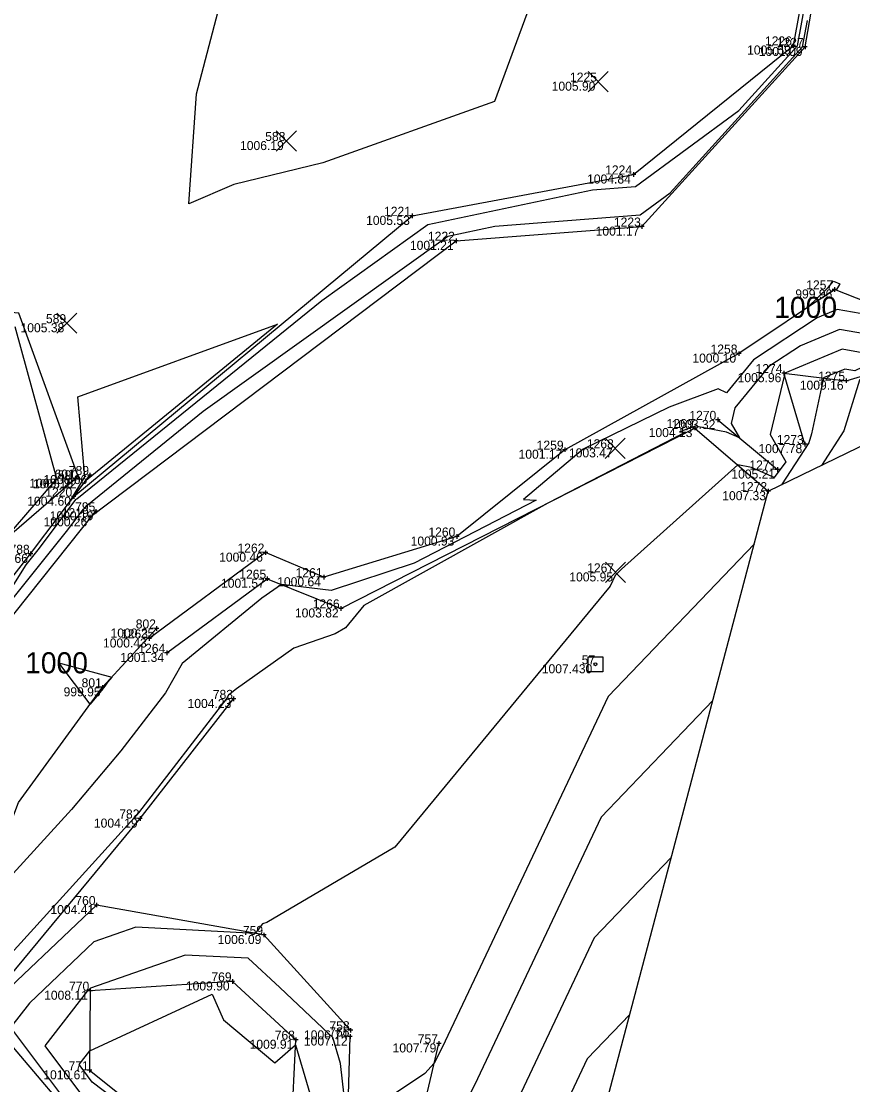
# Model space of a CAD drawing. Extents: x 2354693 to 2355622, y 637071 to 710080.
# Drawn here: x 2355435.7 to 2355546, y 709334.6 to 709475.6 of the extents above; entities that cross this region are included whole.
import ezdxf

# ---------------------------------------------------------------- set-up
doc = ezdxf.new("R2010")
doc.units = 0
for name, color, linetype in [('Default', 7, 'Continuous'), ('DR_X_Ditch', 7, 'Continuous'), ('DT_X_Contour_Major', 7, 'Continuous'), ('DT_X_Contour_Minor', 7, 'Continuous'), ('HY_X_Water_Edge', 7, 'Continuous'), ('SV_X_Control_Cells_Found', 7, 'Continuous'), ('SV_X_Random_Point', 7, 'Continuous'), ('SV_X_Shot_Marker', 7, 'Continuous'), ('SV_X_Text_Elevation', 7, 'Continuous'), ('SV_X_Text_Name', 7, 'Continuous'), ('SV_X_Toe_of_Slope', 7, 'Continuous'), ('SV_X_Top_of_Bank', 7, 'Continuous')]:
    doc.layers.add(name, color=color, linetype=linetype)

msp = doc.modelspace()

# ---------------------------------------------------------------- linework, layer by layer
at = {"layer": 'Default'}
msp.add_lwpolyline([(2355263.76, 708986.4), (2355330.91, 709003.61), (2355347.35, 709002.09), (2355387.45, 709051.54), (2355402.1, 709089.16), (2355425.96, 709130.16), (2355495.56, 709194.41), (2355530.33, 709221.46), (2355525, 709302.12), (2355509.66, 709318.33), (2355534.8, 709413.26), (2355566.11, 709428.47), (2355585.74, 709473.78), (2355589.64, 709532.44), (2355608.23, 709591.27)], dxfattribs=at)
msp.add_lwpolyline([(2355263.76, 708986.4), (2355330.91, 709003.61), (2355347.35, 709002.09), (2355387.45, 709051.54), (2355402.1, 709089.16), (2355425.96, 709130.16), (2355495.56, 709194.41), (2355530.33, 709221.46), (2355525, 709302.12), (2355509.66, 709318.33), (2355534.8, 709413.26), (2355566.11, 709428.47), (2355585.74, 709473.78), (2355589.64, 709532.44), (2355608.23, 709591.27)], dxfattribs=at)
at = {"layer": 'DR_X_Ditch'}
msp.add_line((2355528.1, 709422.71), (2355536.02, 709416.13), dxfattribs=at)
at = {"layer": 'DT_X_Contour_Major'}
for points in [[(2355540.05, 709437.64), (2355542.75, 709440.28), (2355543.44, 709441.12), (2355544.28, 709440.74), (2355543.81, 709439.92), (2355543.58, 709439.96), (2355543.53, 709439.93), (2355540.05, 709437.64)], [(2355540.05, 709437.64), (2355542.75, 709440.28), (2355543.44, 709441.12), (2355544.28, 709440.74), (2355543.81, 709439.92), (2355543.58, 709439.96), (2355543.53, 709439.93), (2355540.05, 709437.64)], [(2355559.54, 709434.37), (2355559.34, 709434.14), (2355548.29, 709428.87), (2355546.89, 709427.96), (2355544.8, 709421.25), (2355541.84, 709416.68)], [(2355559.54, 709434.37), (2355559.34, 709434.14), (2355548.29, 709428.87), (2355546.89, 709427.96), (2355544.8, 709421.25), (2355541.84, 709416.68)], [(2355440.7, 709390.5), (2355447.72, 709388.58), (2355447.16, 709387.95), (2355446.82, 709387.42), (2355446.71, 709387.23), (2355446.56, 709387.04), (2355444.87, 709385.02), (2355440.7, 709390.5)], [(2355440.7, 709390.5), (2355447.72, 709388.58), (2355447.16, 709387.95), (2355446.82, 709387.42), (2355446.71, 709387.23), (2355446.56, 709387.04), (2355444.87, 709385.02), (2355440.7, 709390.5)], [(2355527.44, 709385.48), (2355512.64, 709370.03), (2355495.83, 709334.5), (2355484.62, 709312.4), (2355480.32, 709307.64), (2355473.09, 709303.99)], [(2355527.44, 709385.48), (2355512.64, 709370.03), (2355495.83, 709334.5), (2355484.62, 709312.4), (2355480.32, 709307.64), (2355473.09, 709303.99)], [(2355443.39, 709337.22), (2355444.8, 709339.03), (2355461.03, 709346.58), (2355462.53, 709343.17), (2355469.34, 709337.47), (2355472.1, 709339.84), (2355475.25, 709329.18), (2355476.95, 709313.91), (2355471.7, 709309.42), (2355465.6, 709303.22), (2355462.07, 709308.75), (2355460.83, 709316.09), (2355458.39, 709323.15)], [(2355443.39, 709337.22), (2355444.8, 709339.03), (2355461.03, 709346.58), (2355462.53, 709343.17), (2355469.34, 709337.47), (2355472.1, 709339.84), (2355475.25, 709329.18), (2355476.95, 709313.91), (2355471.7, 709309.42), (2355465.6, 709303.22), (2355462.07, 709308.75), (2355460.83, 709316.09), (2355458.39, 709323.15)], [(2355450.6, 709330.75), (2355445.14, 709334.89), (2355443.39, 709337.22)], [(2355450.6, 709330.75), (2355445.14, 709334.89), (2355443.39, 709337.22)]]:
    msp.add_lwpolyline(points, dxfattribs=at)
at = {"layer": 'DT_X_Contour_Minor'}
for points in [[(2355458.98, 709465.95), (2355468.21, 709501.21), (2355507.67, 709489.91), (2355498.5, 709464.94), (2355475.74, 709456.8), (2355463.93, 709453.92), (2355457.97, 709451.38), (2355458.98, 709465.95)], [(2355458.98, 709465.95), (2355468.21, 709501.21), (2355507.67, 709489.91), (2355498.5, 709464.94), (2355475.74, 709456.8), (2355463.93, 709453.92), (2355457.97, 709451.38), (2355458.98, 709465.95)], [(2355587.59, 709501.58), (2355580.8, 709483.62), (2355581.46, 709475.35), (2355578.77, 709466.39), (2355572.26, 709455.5), (2355563.48, 709441.19), (2355557.75, 709434.69), (2355546.26, 709429.21), (2355544.93, 709429.44), (2355542.14, 709428.27), (2355540.54, 709420.87), (2355540.17, 709419.68), (2355536.57, 709414.12)], [(2355587.59, 709501.58), (2355580.8, 709483.62), (2355581.46, 709475.35), (2355578.77, 709466.39), (2355572.26, 709455.5), (2355563.48, 709441.19), (2355557.75, 709434.69), (2355546.26, 709429.21), (2355544.93, 709429.44), (2355542.14, 709428.27), (2355540.54, 709420.87), (2355540.17, 709419.68), (2355536.57, 709414.12)], [(2355430.17, 709393.7), (2355436.39, 709403.49), (2355438.15, 709405.69), (2355442.98, 709412.15), (2355443.03, 709412.2), (2355443.08, 709412.26), (2355475.57, 709438.56), (2355489.63, 709448.6), (2355511.5, 709453.22), (2355517.19, 709453.67), (2355530.89, 709463.72), (2355538.66, 709472.29), (2355540.72, 709483.47)], [(2355430.17, 709393.7), (2355436.39, 709403.49), (2355438.15, 709405.69), (2355442.98, 709412.15), (2355443.03, 709412.2), (2355443.08, 709412.26), (2355475.57, 709438.56), (2355489.63, 709448.6), (2355511.5, 709453.22), (2355517.19, 709453.67), (2355530.89, 709463.72), (2355538.66, 709472.29), (2355540.72, 709483.47)], [(2355434.67, 709399.07), (2355441.73, 709407.89), (2355443.97, 709410.89), (2355444.19, 709411.1), (2355444.42, 709411.38), (2355459.84, 709423.87), (2355492.32, 709447.07), (2355498.52, 709448.38), (2355517.79, 709449.9), (2355521.8, 709452.84), (2355539.35, 709472.2), (2355539.99, 709475.69)], [(2355434.67, 709399.07), (2355441.73, 709407.89), (2355443.97, 709410.89), (2355444.19, 709411.1), (2355444.42, 709411.38), (2355459.84, 709423.87), (2355492.32, 709447.07), (2355498.52, 709448.38), (2355517.79, 709449.9), (2355521.8, 709452.84), (2355539.35, 709472.2), (2355539.99, 709475.69)], [(2355552.08, 709435.92), (2355543.92, 709437.33), (2355541.3, 709436.23), (2355532.83, 709430.66), (2355529.24, 709426.31), (2355528.14, 709426.84), (2355521.65, 709424.41), (2355510.24, 709418.82), (2355502.32, 709412.16), (2355504.03, 709412.05), (2355487.82, 709403.72), (2355476.82, 709400.08), (2355470.22, 709400.89), (2355467.64, 709399.07), (2355457.06, 709390.42), (2355454.84, 709386.51), (2355448.91, 709378.83), (2355442.39, 709371.05), (2355433.29, 709361.04)], [(2355552.08, 709435.92), (2355543.92, 709437.33), (2355541.3, 709436.23), (2355532.83, 709430.66), (2355529.24, 709426.31), (2355528.14, 709426.84), (2355521.65, 709424.41), (2355510.24, 709418.82), (2355502.32, 709412.16), (2355504.03, 709412.05), (2355487.82, 709403.72), (2355476.82, 709400.08), (2355470.22, 709400.89), (2355467.64, 709399.07), (2355457.06, 709390.42), (2355454.84, 709386.51), (2355448.91, 709378.83), (2355442.39, 709371.05), (2355433.29, 709361.04)], [(2355550.14, 709433.68), (2355544.26, 709434.7), (2355539.07, 709432.53), (2355534.88, 709429.77), (2355530.37, 709424.32), (2355529.87, 709422.22), (2355530.97, 709420.33), (2355529.24, 709421.1), (2355525.52, 709421.8), (2355525.23, 709421.94), (2355523.03, 709421.12), (2355523.81, 709421.07), (2355505.55, 709411.69), (2355481.17, 709398.11), (2355478.71, 709395.14), (2355477.34, 709394.33), (2355471.88, 709392.44), (2355464.27, 709387.07), (2355463.2, 709386.19), (2355462.97, 709385.8), (2355451.26, 709370.62), (2355450.71, 709369.95), (2355430.88, 709348.16)], [(2355550.14, 709433.68), (2355544.26, 709434.7), (2355539.07, 709432.53), (2355534.88, 709429.77), (2355530.37, 709424.32), (2355529.87, 709422.22), (2355530.97, 709420.33), (2355529.24, 709421.1), (2355525.52, 709421.8), (2355525.23, 709421.94), (2355523.03, 709421.12), (2355523.81, 709421.07), (2355505.55, 709411.69), (2355481.17, 709398.11), (2355478.71, 709395.14), (2355477.34, 709394.33), (2355471.88, 709392.44), (2355464.27, 709387.07), (2355463.2, 709386.19), (2355462.97, 709385.8), (2355451.26, 709370.62), (2355450.71, 709369.95), (2355430.88, 709348.16)], [(2355433.6, 709406.92), (2355440.44, 709414.89), (2355434.9, 709435.05)], [(2355433.6, 709406.92), (2355440.44, 709414.89), (2355434.9, 709435.05)], [(2355444.13, 709414.48), (2355442.22, 709411.94), (2355444.16, 709415.14), (2355443.25, 709425.76), (2355469.69, 709435.4), (2355444.13, 709414.48)], [(2355444.13, 709414.48), (2355442.22, 709411.94), (2355444.16, 709415.14), (2355443.25, 709425.76), (2355469.69, 709435.4), (2355444.13, 709414.48)], [(2355548.2, 709431.44), (2355544.6, 709432.07), (2355537, 709428.89), (2355536.95, 709428.68), (2355535.05, 709420.78), (2355537.14, 709417.17), (2355535.57, 709415.06), (2355532.58, 709416.39), (2355530.75, 709416.74), (2355515.32, 709402.92), (2355514.5, 709402.06), (2355513.83, 709400.65), (2355485.25, 709366.06), (2355468.29, 709356.07), (2355467.71, 709355.87), (2355467.15, 709355.12), (2355466.75, 709354.61), (2355450.92, 709355.44), (2355445.35, 709353.49), (2355436.8, 709345.36), (2355434.3, 709342.15), (2355447.56, 709324.46)], [(2355548.2, 709431.44), (2355544.6, 709432.07), (2355537, 709428.89), (2355536.95, 709428.68), (2355535.05, 709420.78), (2355537.14, 709417.17), (2355535.57, 709415.06), (2355532.58, 709416.39), (2355530.75, 709416.74), (2355515.32, 709402.92), (2355514.5, 709402.06), (2355513.83, 709400.65), (2355485.25, 709366.06), (2355468.29, 709356.07), (2355467.71, 709355.87), (2355467.15, 709355.12), (2355466.75, 709354.61), (2355450.92, 709355.44), (2355445.35, 709353.49), (2355436.8, 709345.36), (2355434.3, 709342.15), (2355447.56, 709324.46)], [(2355532.95, 709406.29), (2355513.57, 709386.04), (2355491.55, 709339.51), (2355490.49, 709337.41), (2355489.24, 709336.03), (2355479, 709329.17), (2355478.08, 709337.35), (2355477.06, 709340.81), (2355476.51, 709341.28), (2355470.02, 709347.46), (2355465.8, 709351.32), (2355457.48, 709351.75), (2355444.91, 709347.35), (2355444.47, 709346.94), (2355438.85, 709339.69), (2355446.35, 709329.67)], [(2355532.95, 709406.29), (2355513.57, 709386.04), (2355491.55, 709339.51), (2355490.49, 709337.41), (2355489.24, 709336.03), (2355479, 709329.17), (2355478.08, 709337.35), (2355477.06, 709340.81), (2355476.51, 709341.28), (2355470.02, 709347.46), (2355465.8, 709351.32), (2355457.48, 709351.75), (2355444.91, 709347.35), (2355444.47, 709346.94), (2355438.85, 709339.69), (2355446.35, 709329.67)], [(2355521.93, 709364.68), (2355511.72, 709354.01), (2355500.11, 709329.49)], [(2355521.93, 709364.68), (2355511.72, 709354.01), (2355500.11, 709329.49)], [(2355516.42, 709343.87), (2355510.79, 709337.99), (2355504.4, 709324.48)], [(2355516.42, 709343.87), (2355510.79, 709337.99), (2355504.4, 709324.48)]]:
    msp.add_lwpolyline(points, dxfattribs=at)
at = {"layer": 'HY_X_Water_Edge'}
for points in [[(2355444.84, 709409.8), (2355493.39, 709446.46), (2355518.03, 709448.34), (2355539.67, 709472.16), (2355542.83, 709490.32), (2355537.69, 709525.78), (2355546.35, 709545.98), (2355551.46, 709553.96), (2355570.39, 709576.73), (2355584.11, 709603.77), (2355585.55, 709628.29), (2355564.78, 709662.12), (2355552.11, 709684.77), (2355549.62, 709715.93), (2355559.81, 709748.25), (2355589.77, 709771.03)], [(2355601.98, 709641.84), (2355600.27, 709603.87), (2355587.93, 709575.67), (2355574.93, 709552.02), (2355564.16, 709527.42), (2355560.86, 709513.6), (2355569.23, 709466.41), (2355552.57, 709436.48), (2355543.58, 709440.01), (2355530.89, 709431.5), (2355507.81, 709418.76), (2355493.48, 709407.24), (2355475.84, 709401.85), (2355468.12, 709405.11), (2355452.68, 709393.73)], [(2355352.91, 709352.05), (2355379.29, 709352.51), (2355413.25, 709365.62), (2355415.95, 709373.64), (2355433.01, 709394.8), (2355445.63, 709410.59)], [(2355375.81, 709279.18), (2355398.04, 709300.45), (2355412.55, 709325.04), (2355426.37, 709348.2), (2355435.34, 709371.97), (2355446.5, 709387.25), (2355453.68, 709395.05)]]:
    msp.add_lwpolyline(points, dxfattribs=at)
at = {"layer": 'SV_X_Control_Cells_Found'}
msp.add_lwpolyline([(2355510.89, 709391.3), (2355512.87, 709391.3), (2355512.87, 709389.32), (2355510.89, 709389.32), (2355510.89, 709391.3)], dxfattribs=at)
msp.add_circle((2355511.88, 709390.31), 0.2, dxfattribs=at)
at = {"layer": 'SV_X_Random_Point'}
for p, q in [((2355510.89, 709466.22), (2355513.56, 709468.89)), ((2355510.89, 709468.89), (2355513.56, 709466.22)), ((2355469.54, 709458.35), (2355472.21, 709461.02)), ((2355469.54, 709461.02), (2355472.21, 709458.35)), ((2355440.44, 709434.19), (2355443.11, 709436.86)), ((2355440.44, 709436.86), (2355443.11, 709434.19)), ((2355513.16, 709417.6), (2355515.83, 709420.27)), ((2355513.16, 709420.27), (2355515.83, 709417.6)), ((2355513.19, 709401.16), (2355515.85, 709403.83)), ((2355513.19, 709403.83), (2355515.85, 709401.16))]:
    msp.add_line(p, q, dxfattribs=at)
at = {"layer": 'SV_X_Shot_Marker'}
for p, q in [((2355538.12, 709472.66), (2355538.12, 709472.06)), ((2355539.67, 709472.46), (2355539.67, 709471.86)), ((2355538.42, 709472.36), (2355537.82, 709472.36)), ((2355539.97, 709472.16), (2355539.37, 709472.16)), ((2355516.94, 709455.55), (2355516.94, 709454.95)), ((2355517.24, 709455.25), (2355516.64, 709455.25)), ((2355487.57, 709450.07), (2355487.57, 709449.47)), ((2355487.87, 709449.77), (2355487.27, 709449.77)), ((2355518.03, 709448.64), (2355518.03, 709448.04)), ((2355518.33, 709448.34), (2355517.73, 709448.34)), ((2355493.69, 709446.46), (2355493.09, 709446.46)), ((2355493.39, 709446.76), (2355493.39, 709446.16)), ((2355543.88, 709440.01), (2355543.28, 709440.01)), ((2355543.58, 709440.31), (2355543.58, 709439.71)), ((2355530.89, 709431.8), (2355530.89, 709431.2)), ((2355531.19, 709431.5), (2355530.59, 709431.5)), ((2355537.18, 709428.91), (2355536.58, 709428.91)), ((2355536.88, 709429.21), (2355536.88, 709428.61)), ((2355545.43, 709427.91), (2355544.83, 709427.91)), ((2355545.13, 709428.21), (2355545.13, 709427.61)), ((2355525.05, 709421.93), (2355525.05, 709421.33)), ((2355528.4, 709422.71), (2355527.8, 709422.71)), ((2355528.1, 709423.01), (2355528.1, 709422.41)), ((2355525.35, 709421.63), (2355524.75, 709421.63)), ((2355507.81, 709419.06), (2355507.81, 709418.46)), ((2355539.95, 709419.5), (2355539.35, 709419.5)), ((2355539.65, 709419.8), (2355539.65, 709419.2)), ((2355508.11, 709418.76), (2355507.52, 709418.76)), ((2355536.32, 709416.13), (2355535.72, 709416.13)), ((2355536.02, 709416.43), (2355536.02, 709415.83)), ((2355443.21, 709414.92), (2355442.61, 709414.92)), ((2355442.91, 709415.22), (2355442.91, 709414.62)), ((2355443.69, 709414.83), (2355443.09, 709414.83)), ((2355443.39, 709415.13), (2355443.39, 709414.53)), ((2355445.12, 709415.4), (2355444.52, 709415.4)), ((2355444.82, 709415.7), (2355444.82, 709415.1)), ((2355535.1, 709413.26), (2355534.5, 709413.26)), ((2355534.8, 709413.56), (2355534.8, 709412.96)), ((2355442.98, 709412.53), (2355442.38, 709412.53)), ((2355442.68, 709412.83), (2355442.68, 709412.23)), ((2355445.93, 709410.59), (2355445.33, 709410.59)), ((2355445.63, 709410.89), (2355445.63, 709410.29)), ((2355445.14, 709409.8), (2355444.54, 709409.8)), ((2355444.84, 709410.1), (2355444.84, 709409.5)), ((2355493.78, 709407.24), (2355493.18, 709407.24)), ((2355493.48, 709407.54), (2355493.48, 709406.94)), ((2355437.26, 709404.95), (2355436.66, 709404.95)), ((2355436.96, 709405.25), (2355436.96, 709404.65)), ((2355468.42, 709405.11), (2355467.82, 709405.11)), ((2355468.12, 709405.41), (2355468.12, 709404.81)), ((2355468.36, 709401.95), (2355468.36, 709401.35)), ((2355475.84, 709402.15), (2355475.84, 709401.55)), ((2355468.66, 709401.65), (2355468.06, 709401.65)), ((2355476.14, 709401.85), (2355475.54, 709401.85)), ((2355478.43, 709397.71), (2355477.83, 709397.71)), ((2355478.13, 709398.01), (2355478.13, 709397.41)), ((2355453.98, 709395.05), (2355453.38, 709395.05)), ((2355453.68, 709395.35), (2355453.68, 709394.75)), ((2355452.98, 709393.73), (2355452.38, 709393.73)), ((2355452.68, 709394.03), (2355452.68, 709393.43)), ((2355455.03, 709392.12), (2355455.03, 709391.52)), ((2355455.33, 709391.82), (2355454.73, 709391.82)), ((2355446.8, 709387.25), (2355446.2, 709387.25)), ((2355446.5, 709387.55), (2355446.5, 709386.95)), ((2355464.19, 709385.71), (2355463.59, 709385.71)), ((2355463.89, 709386.01), (2355463.89, 709385.41)), ((2355451.78, 709369.85), (2355451.18, 709369.85)), ((2355451.48, 709370.15), (2355451.48, 709369.55)), ((2355446.01, 709358.38), (2355445.41, 709358.38)), ((2355445.71, 709358.68), (2355445.71, 709358.08)), ((2355468.2, 709354.41), (2355467.6, 709354.41)), ((2355467.9, 709354.71), (2355467.9, 709354.11)), ((2355463.72, 709348.55), (2355463.72, 709347.95)), ((2355445.18, 709347.02), (2355444.58, 709347.02)), ((2355444.88, 709347.32), (2355444.88, 709346.72)), ((2355464.02, 709348.25), (2355463.42, 709348.25)), ((2355479.69, 709341.77), (2355479.09, 709341.77)), ((2355479.39, 709342.07), (2355479.39, 709341.47)), ((2355472.43, 709340.52), (2355471.83, 709340.52)), ((2355472.13, 709340.82), (2355472.13, 709340.22)), ((2355479.63, 709340.95), (2355479.03, 709340.95)), ((2355479.33, 709341.25), (2355479.33, 709340.65)), ((2355491.4, 709340.03), (2355490.8, 709340.03)), ((2355491.1, 709340.33), (2355491.1, 709339.73)), ((2355445.07, 709336.47), (2355444.47, 709336.47)), ((2355444.77, 709336.77), (2355444.77, 709336.17))]:
    msp.add_line(p, q, dxfattribs=at)
at = {"layer": 'SV_X_Toe_of_Slope'}
for points in [[(2355444.84, 709409.8), (2355493.39, 709446.46), (2355518.03, 709448.34), (2355539.67, 709472.16), (2355542.83, 709490.32), (2355537.69, 709525.78), (2355546.35, 709545.98), (2355551.46, 709553.96), (2355570.39, 709576.73), (2355584.11, 709603.77), (2355585.55, 709628.29), (2355564.78, 709662.12), (2355552.11, 709684.77), (2355549.62, 709715.93), (2355559.81, 709748.25), (2355589.77, 709771.03)], [(2355601.98, 709641.84), (2355600.27, 709603.87), (2355587.93, 709575.67), (2355574.93, 709552.02), (2355564.16, 709527.42), (2355560.86, 709513.6), (2355569.23, 709466.41), (2355552.57, 709436.48), (2355543.58, 709440.01), (2355530.89, 709431.5), (2355507.81, 709418.76), (2355493.48, 709407.24), (2355475.84, 709401.85), (2355468.12, 709405.11), (2355452.68, 709393.73)], [(2355443.39, 709414.83), (2355435.4, 709436.85), (2355409.19, 709439.12), (2355397.79, 709453.17), (2355374.7, 709435.72), (2355372.91, 709411.58), (2355376.75, 709386.62), (2355393.34, 709368.52), (2355409.05, 709375.59), (2355424.99, 709391.99), (2355430.56, 709404.29), (2355442.91, 709414.92)], [(2355352.91, 709352.05), (2355379.29, 709352.51), (2355413.25, 709365.62), (2355415.95, 709373.64), (2355433.01, 709394.8), (2355445.63, 709410.59)], [(2355375.81, 709279.18), (2355398.04, 709300.45), (2355412.55, 709325.04), (2355426.37, 709348.2), (2355435.34, 709371.97), (2355446.5, 709387.25), (2355453.68, 709395.05)], [(2355479.39, 709341.77), (2355467.9, 709354.41), (2355445.71, 709358.38), (2355430.69, 709344.11), (2355447.63, 709324.14), (2355466.16, 709301.29), (2355478.54, 709313.08), (2355479.33, 709340.95)], [(2355474.64, 709251.99), (2355482.17, 709301.94), (2355491.1, 709340.03)]]:
    msp.add_lwpolyline(points, dxfattribs=at)
at = {"layer": 'SV_X_Top_of_Bank'}
for points in [[(2355539.65, 709419.5), (2355536.88, 709428.91), (2355545.13, 709427.91), (2355562.31, 709433.11), (2355572.18, 709444.95), (2355572.3, 709459.52), (2355577.24, 709476.89), (2355570.97, 709503.21), (2355563.87, 709514.15), (2355574.03, 709537.88), (2355587.83, 709570.74), (2355601.3, 709594.65), (2355608.86, 709626.36), (2355614.36, 709652.49)], [(2355442.68, 709412.53), (2355487.57, 709449.77), (2355516.94, 709455.25), (2355538.12, 709472.36), (2355541.27, 709489.43), (2355534.29, 709527.27), (2355537.01, 709547.49), (2355527.94, 709562.59)], [(2355455.03, 709391.82), (2355468.36, 709401.65), (2355478.13, 709397.71), (2355525.05, 709421.63), (2355534.8, 709413.26)], [(2355367.94, 709364.17), (2355396.21, 709369.55), (2355410.01, 709376.64), (2355427.27, 709392.59), (2355436.96, 709404.95), (2355444.82, 709415.4)], [(2355402.87, 709193.94), (2355398.04, 709239.15), (2355396.02, 709270.95), (2355396.93, 709276.49), (2355405.83, 709286.83), (2355411.15, 709299.51), (2355425.92, 709328.9), (2355430.11, 709344.03), (2355451.48, 709369.85), (2355463.89, 709385.71)], [(2355464.86, 709305.77), (2355471.01, 709316.99), (2355472.13, 709340.52), (2355463.72, 709348.25), (2355444.88, 709347.02), (2355444.77, 709336.47), (2355458.43, 709325.57), (2355466.19, 709312.83)]]:
    msp.add_lwpolyline(points, dxfattribs=at)

# ---------------------------------------------------------------- texts
at = {"layer": 'DT_X_Contour_Major'}
for p in [(2355535.59, 709436.24), (2355535.59, 709436.24), (2355436.24, 709389.1), (2355436.24, 709389.1)]:
    msp.add_text('1000', height=2.8, dxfattribs=at).set_placement(p)
at = {"layer": 'SV_X_Text_Elevation'}
for s, p in [('1005.59', (2355531.99, 709471.16)), ('1001.09', (2355533.54, 709470.96)), ('1005.90', (2355506.07, 709466.36)), ('1006.19', (2355464.74, 709458.49)), ('1004.84', (2355510.77, 709454.05)), ('1005.53', (2355481.46, 709448.57)), ('1001.17', (2355511.9, 709447.14)), ('1001.21', (2355487.27, 709445.26)), ('999.96', (2355538.38, 709438.81)), ('1005.38', (2355435.63, 709434.33)), ('1000.10', (2355524.73, 709430.3)), ('1005.96', (2355530.73, 709427.71)), ('1009.16', (2355538.98, 709426.71)), ('1004.13', (2355518.94, 709420.43)), ('1003.32', (2355521.98, 709421.51)), ('1003.47', (2355508.36, 709417.74)), ('1007.78', (2355533.5, 709418.3)), ('1001.17', (2355501.68, 709417.56)), ('1005.21', (2355529.9, 709414.93)), ('1005.15', (2355436.8, 709413.72)), ('1005.22', (2355437.27, 709413.63)), ('1006.66', (2355438.67, 709414.2)), ('1007.33', (2355528.69, 709412.06)), ('1004.60', (2355436.52, 709411.33)), ('1000.19', (2355439.5, 709409.39)), ('1000.26', (2355438.69, 709408.6)), ('1000.93', (2355487.37, 709406.04)), ('1004.66', (2355430.81, 709403.75)), ('1000.46', (2355461.97, 709403.91)), ('1005.95', (2355508.41, 709401.29)), ('1001.57', (2355462.22, 709400.45)), ('1000.64', (2355469.67, 709400.65)), ('1003.82', (2355472.02, 709396.51)), ('1000.25', (2355447.57, 709393.85)), ('1000.43', (2355446.57, 709392.53)), ('1001.34', (2355448.86, 709390.62)), ('1007.430', (2355504.76, 709389.11)), ('999.95', (2355441.34, 709386.05)), ('1004.23', (2355457.78, 709384.51)), ('1004.19', (2355445.36, 709368.65)), ('1004.41', (2355439.59, 709357.18)), ('1006.09', (2355461.77, 709353.21)), ('1008.11', (2355438.76, 709345.82)), ('1009.90', (2355457.56, 709347.05)), ('1006.74', (2355473.22, 709340.57)), ('1009.91', (2355466.01, 709339.32)), ('1007.12', (2355473.21, 709339.75)), ('1007.79', (2355484.97, 709338.83)), ('1010.61', (2355438.65, 709335.27))]:
    msp.add_text(s, height=1.2, dxfattribs=at).set_placement(p)
at = {"layer": 'SV_X_Text_Name'}
for s, p in [('1226', (2355534.36, 709472.36)), ('1227', (2355535.92, 709472.16)), ('1225', (2355508.5, 709467.56)), ('588', (2355468.08, 709459.69)), ('1224', (2355513.16, 709455.25)), ('1221', (2355483.84, 709449.77)), ('1223', (2355514.32, 709448.34)), ('1222', (2355489.66, 709446.46)), ('1257', (2355539.83, 709440.01)), ('589', (2355439, 709435.53)), ('1258', (2355527.14, 709431.5)), ('1274', (2355533.11, 709428.91)), ('1275', (2355541.41, 709427.91)), ('1270', (2355524.33, 709422.71)), ('1269', (2355521.32, 709421.63)), ('1273', (2355535.93, 709419.5)), ('1259', (2355504.08, 709418.76)), ('1268', (2355510.74, 709418.94)), ('601', (2355440.14, 709414.92)), ('590', (2355440.59, 709414.83)), ('789', (2355442.04, 709415.4)), ('1271', (2355532.29, 709416.13)), ('1220', (2355438.91, 709412.53)), ('1272', (2355531.07, 709413.26)), ('795', (2355442.87, 709410.59)), ('1219', (2355441.1, 709409.8)), ('1260', (2355489.72, 709407.24)), ('788', (2355434.17, 709404.95)), ('1262', (2355464.4, 709405.11)), ('1267', (2355510.78, 709402.49)), ('1265', (2355464.64, 709401.65)), ('1261', (2355472.11, 709401.85)), ('1266', (2355474.38, 709397.71)), ('802', (2355450.91, 709395.05)), ('1263', (2355448.96, 709393.73)), ('1264', (2355451.25, 709391.82)), ('57', (2355510.05, 709390.31)), ('801', (2355443.73, 709387.25)), ('783', (2355461.13, 709385.71)), ('782', (2355448.72, 709369.85)), ('760', (2355442.9, 709358.38)), ('759', (2355465.12, 709354.41)), ('769', (2355460.94, 709348.25)), ('770', (2355442.07, 709347.02)), ('758', (2355476.6, 709341.77)), ('768', (2355469.34, 709340.52)), ('765', (2355476.57, 709340.95)), ('757', (2355488.31, 709340.03)), ('771', (2355442, 709336.47))]:
    msp.add_text(s, height=1.2, dxfattribs=at).set_placement(p)

doc.saveas('drawing.dxf')
